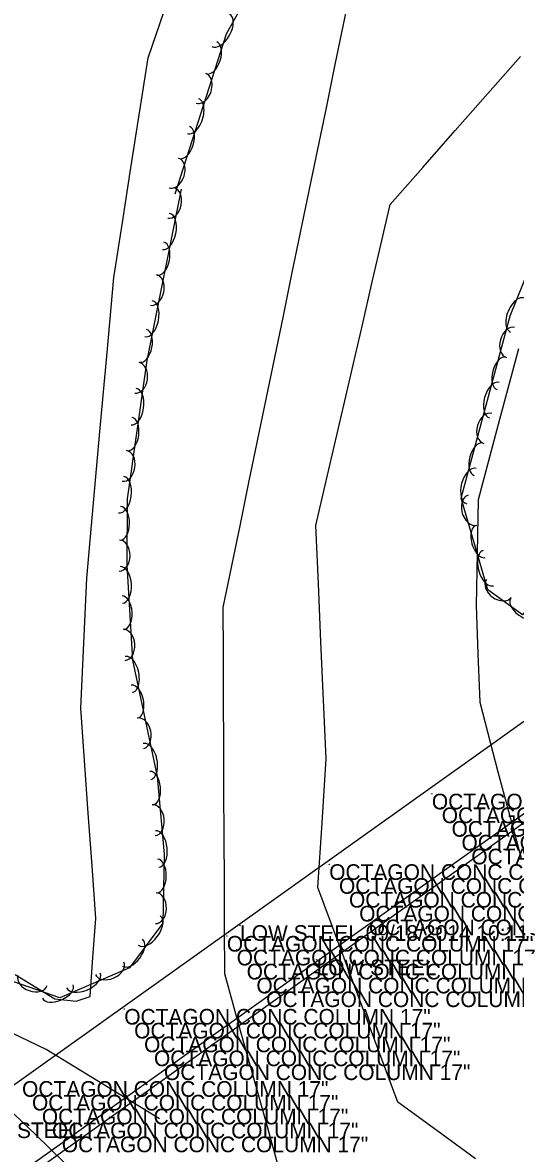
# Model space of a CAD drawing. Extents: x 1451369 to 1458940, y 1868647 to 1875095.
# Drawn here: x 1454280 to 1454437.4, y 1871458.6 to 1871820 of the extents above; entities that cross this region are included whole.
import ezdxf

# ---------------------------------------------------------------- set-up
doc = ezdxf.new("R2010")
doc.units = 0
for name, color, linetype in [('E_Existing_ROW', 7, 'Continuous'), ('E_Proposed ROW and Easements', 7, 'Continuous'), ('E_Quarter Section Line', 7, 'Continuous'), ('E_ROW Point Number', 7, 'Continuous'), ('E_Tract Residual', 7, 'Continuous'), ('S_EXIST_ROW', 7, 'Continuous'), ('S_MISC_STRUCTURES_ANNOT', 7, 'Continuous')]:
    doc.layers.add(name, color=color, linetype=linetype)

msp = doc.modelspace()

# ---------------------------------------------------------------- linework, layer by layer
at = {"layer": 'E_Existing_ROW'}
for p, q in [((1454539.16, 1871667.36), (1454213.66, 1871435.13)), ((1454227.64, 1871415.7), (1454553.13, 1871647.85))]:
    msp.add_line(p, q, dxfattribs=at)
at = {"layer": 'E_Proposed ROW and Easements'}
for points in [[(1454410.69, 1871573.56), (1454410.69, 1871573.61), (1454410.69, 1871573.56), (1454410.64, 1871573.56), (1454410.69, 1871573.56), (1454410.69, 1871573.51), (1454410.69, 1871573.56), (1454410.74, 1871573.56)], [(1454413.85, 1871569.17), (1454413.85, 1871569.22), (1454413.85, 1871569.17), (1454413.8, 1871569.17), (1454413.85, 1871569.17), (1454413.85, 1871569.12), (1454413.85, 1871569.17), (1454413.9, 1871569.17)], [(1454416.98, 1871564.83), (1454416.98, 1871564.88), (1454416.98, 1871564.83), (1454416.93, 1871564.83), (1454416.98, 1871564.83), (1454416.98, 1871564.78), (1454416.98, 1871564.83), (1454417.03, 1871564.83)], [(1454420.15, 1871560.41), (1454420.15, 1871560.46), (1454420.15, 1871560.41), (1454420.1, 1871560.41), (1454420.15, 1871560.41), (1454420.15, 1871560.36), (1454420.15, 1871560.41), (1454420.2, 1871560.41)], [(1454423.29, 1871555.99), (1454423.29, 1871556.04), (1454423.29, 1871555.99), (1454423.24, 1871555.99), (1454423.29, 1871555.99), (1454423.29, 1871555.94), (1454423.29, 1871555.99), (1454423.34, 1871555.99)], [(1454377.9, 1871551.02), (1454377.9, 1871551.07), (1454377.9, 1871551.02), (1454377.85, 1871551.02), (1454377.9, 1871551.02), (1454377.9, 1871550.97), (1454377.9, 1871551.02), (1454377.95, 1871551.02)], [(1454381.03, 1871546.59), (1454381.03, 1871546.64), (1454381.03, 1871546.59), (1454380.98, 1871546.59), (1454381.03, 1871546.59), (1454381.03, 1871546.54), (1454381.03, 1871546.59), (1454381.08, 1871546.59)], [(1454384.22, 1871542.16), (1454384.22, 1871542.21), (1454384.22, 1871542.16), (1454384.17, 1871542.16), (1454384.22, 1871542.16), (1454384.22, 1871542.11), (1454384.22, 1871542.16), (1454384.27, 1871542.16)], [(1454387.47, 1871537.73), (1454387.47, 1871537.78), (1454387.47, 1871537.73), (1454387.42, 1871537.73), (1454387.47, 1871537.73), (1454387.47, 1871537.68), (1454387.47, 1871537.73), (1454387.52, 1871537.73)], [(1454349.45, 1871531.54), (1454349.45, 1871531.59), (1454349.45, 1871531.54), (1454349.4, 1871531.54), (1454349.45, 1871531.54), (1454349.45, 1871531.49), (1454349.45, 1871531.54), (1454349.5, 1871531.54)], [(1454390.57, 1871533.33), (1454390.57, 1871533.38), (1454390.57, 1871533.33), (1454390.52, 1871533.33), (1454390.57, 1871533.33), (1454390.57, 1871533.28), (1454390.57, 1871533.33), (1454390.62, 1871533.33)], [(1454345.22, 1871528.1), (1454345.22, 1871528.15), (1454345.22, 1871528.1), (1454345.17, 1871528.1), (1454345.22, 1871528.1), (1454345.22, 1871528.05), (1454345.22, 1871528.1), (1454345.27, 1871528.1)], [(1454348.37, 1871523.69), (1454348.37, 1871523.74), (1454348.37, 1871523.69), (1454348.32, 1871523.69), (1454348.37, 1871523.69), (1454348.37, 1871523.64), (1454348.37, 1871523.69), (1454348.42, 1871523.69)], [(1454373.88, 1871520.55), (1454373.88, 1871520.6), (1454373.88, 1871520.55), (1454373.83, 1871520.55), (1454373.88, 1871520.55), (1454373.88, 1871520.5), (1454373.88, 1871520.55), (1454373.93, 1871520.55)], [(1454351.55, 1871519.2), (1454351.55, 1871519.25), (1454351.55, 1871519.2), (1454351.5, 1871519.2), (1454351.55, 1871519.2), (1454351.55, 1871519.15), (1454351.55, 1871519.2), (1454351.6, 1871519.2)], [(1454354.66, 1871514.74), (1454354.66, 1871514.79), (1454354.66, 1871514.74), (1454354.61, 1871514.74), (1454354.66, 1871514.74), (1454354.66, 1871514.69), (1454354.66, 1871514.74), (1454354.71, 1871514.74)], [(1454357.77, 1871510.37), (1454357.77, 1871510.42), (1454357.77, 1871510.37), (1454357.72, 1871510.37), (1454357.77, 1871510.37), (1454357.77, 1871510.32), (1454357.77, 1871510.37), (1454357.82, 1871510.37)], [(1454312.46, 1871504.77), (1454312.46, 1871504.82), (1454312.46, 1871504.77), (1454312.41, 1871504.77), (1454312.46, 1871504.77), (1454312.46, 1871504.72), (1454312.46, 1871504.77), (1454312.51, 1871504.77)], [(1454315.62, 1871500.34), (1454315.62, 1871500.39), (1454315.62, 1871500.34), (1454315.57, 1871500.34), (1454315.62, 1871500.34), (1454315.62, 1871500.29), (1454315.62, 1871500.34), (1454315.67, 1871500.34)], [(1454318.79, 1871495.92), (1454318.79, 1871495.97), (1454318.79, 1871495.92), (1454318.74, 1871495.92), (1454318.79, 1871495.92), (1454318.79, 1871495.87), (1454318.79, 1871495.92), (1454318.84, 1871495.92)], [(1454321.96, 1871491.48), (1454321.96, 1871491.53), (1454321.96, 1871491.48), (1454321.91, 1871491.48), (1454321.96, 1871491.48), (1454321.96, 1871491.43), (1454321.96, 1871491.48), (1454322.01, 1871491.48)], [(1454325.16, 1871487.04), (1454325.16, 1871487.09), (1454325.16, 1871487.04), (1454325.11, 1871487.04), (1454325.16, 1871487.04), (1454325.16, 1871486.99), (1454325.16, 1871487.04), (1454325.21, 1871487.04)], [(1454282.99, 1871477.31), (1454282.99, 1871477.36), (1454282.99, 1871477.31), (1454282.94, 1871477.31), (1454282.99, 1871477.31), (1454282.99, 1871477.26), (1454282.99, 1871477.31), (1454283.04, 1871477.31)], [(1454286.15, 1871472.87), (1454286.15, 1871472.92), (1454286.15, 1871472.87), (1454286.1, 1871472.87), (1454286.15, 1871472.87), (1454286.15, 1871472.82), (1454286.15, 1871472.87), (1454286.2, 1871472.87)], [(1454289.38, 1871468.41), (1454289.38, 1871468.46), (1454289.38, 1871468.41), (1454289.33, 1871468.41), (1454289.38, 1871468.41), (1454289.38, 1871468.36), (1454289.38, 1871468.41), (1454289.43, 1871468.41)], [(1454292.52, 1871463.97), (1454292.52, 1871464.02), (1454292.52, 1871463.97), (1454292.47, 1871463.97), (1454292.52, 1871463.97), (1454292.52, 1871463.92), (1454292.52, 1871463.97), (1454292.57, 1871463.97)]]:
    msp.add_lwpolyline(points, dxfattribs=at)
at = {"layer": 'E_Quarter Section Line'}
msp.add_line((1454551.64, 1871643.91), (1454234.22, 1871417.39), dxfattribs=at)
at = {"layer": 'E_ROW Point Number'}
for points in [[(1454474.53, 1872009.99), (1454468.45, 1871992.6), (1454458.03, 1871972.85), (1454441.05, 1871961.61), (1454416.35, 1871957.74), (1454397.06, 1871942.33), (1454383.25, 1871898.18), (1454368.69, 1871851.44), (1454357.73, 1871839.38), (1454344.98, 1871816.3), (1454328.66, 1871765.24)], [(1454738.31, 1871861.57), (1454708.8, 1871816.51), (1454693.32, 1871798.23), (1454669.26, 1871779.8), (1454629.46, 1871765.26), (1454608.9, 1871751.18), (1454586.75, 1871730.8), (1454560.06, 1871707.57), (1454538.95, 1871692.69), (1454521.86, 1871681.88), (1454502.43, 1871685.05), (1454482.33, 1871693.58), (1454468.83, 1871697.08), (1454462.33, 1871676.27), (1454453.21, 1871647.56), (1454439.65, 1871630.76), (1454428.53, 1871638.78), (1454420.08, 1871668), (1454435.67, 1871726.35), (1454455.54, 1871775.31), (1454484.24, 1871834.95)], [(1454330.64, 1871766.81), (1454319.69, 1871712.03), (1454313.42, 1871667.8), (1454313.27, 1871646.67), (1454315.11, 1871616.29), (1454322.93, 1871579.03), (1454325.24, 1871554.26), (1454324.81, 1871532.17), (1454314.16, 1871517.96), (1454291.89, 1871508.3), (1454234.83, 1871528.11)]]:
    msp.add_lwpolyline(points, dxfattribs=at)
for centre, major_axis, ratio, start_param, end_param in [((1454343.27, 1871817.57), (2.84, 5.14), 0.548521, 3.141593, 6.283185), ((1454340.35, 1871808.77), (1.62, 5.09), 0.539409, 3.140213, 6.281805), ((1454336.97, 1871799.04), (1.5, 4.72), 0.683674, 3.139264, 6.280857), ((1454334.4, 1871790.14), (1.78, 5.59), 0.548767, 3.140168, 6.281761), ((1454331.7, 1871781.7), (1.62, 5.09), 0.539409, 3.140213, 6.281805), ((1454328.32, 1871771.97), (1.5, 4.72), 0.683674, 3.139264, 6.280857), ((1454327.33, 1871762.42), (0.97, 4.86), 0.68531, 3.141593, 6.283185), ((1454325.77, 1871753.29), (1.15, 5.75), 0.550079, 3.141593, 6.283185), ((1454324.04, 1871744.59), (1.05, 5.24), 0.540699, 3.141593, 6.283185), ((1454321.76, 1871734.54), (0.97, 4.86), 0.68531, 3.141593, 6.283185), ((1454320.2, 1871725.41), (1.15, 5.75), 0.550079, 3.141593, 6.283185), ((1454438.03, 1871726.53), (-2.21, -5.44), 0.550022, 3.141578, 6.283171), ((1454435.85, 1871717.81), (-1.28, -4.79), 0.685234, 3.141593, 6.283185), ((1454318.46, 1871716.71), (1.05, 5.24), 0.540699, 3.141593, 6.283185), ((1454432.94, 1871707.92), (-1.38, -5.17), 0.540639, 3.141593, 6.283185), ((1454316.49, 1871706.47), (0.69, 4.91), 0.68531, 3.141593, 6.283185), ((1454430.65, 1871699.36), (-1.51, -5.67), 0.550018, 3.141593, 6.283185), ((1454315.45, 1871697.27), (0.82, 5.81), 0.550079, 3.141593, 6.283185), ((1454314.21, 1871688.49), (0.75, 5.29), 0.540699, 3.141593, 6.283185), ((1454428.52, 1871690.34), (-1.28, -4.79), 0.685234, 3.141593, 6.283185), ((1454312.51, 1871678.33), (0.69, 4.91), 0.68531, 3.141593, 6.283185), ((1454425.6, 1871680.46), (-1.38, -5.17), 0.540639, 3.141593, 6.283185), ((1454423.32, 1871671.89), (-1.51, -5.67), 0.550018, 3.141593, 6.283185), ((1454311.47, 1871669.12), (0.82, 5.81), 0.550079, 3.141593, 6.283185), ((1454423.66, 1871664.18), (1.38, -4.76), 0.685288, 3.141813, 6.283406), ((1454311.25, 1871659.98), (0.04, 5.35), 0.540698, 3.141593, 6.283185), ((1454426.27, 1871654.21), (1.48, -5.14), 0.540681, 3.141723, 6.283316), ((1454310.91, 1871649.68), (0.04, 4.96), 0.685308, 3.141593, 6.283185), ((1454428.74, 1871645.7), (1.63, -5.64), 0.550061, 3.141727, 6.28332), ((1454311.53, 1871640.29), (-0.35, 5.86), 0.550077, 3.141593, 6.283185), ((1454432.07, 1871639.17), (3.97, -2.87), 0.693211, 3.143251, 6.284843), ((1454312.07, 1871631.44), (-0.32, 5.34), 0.540697, 3.141593, 6.283185), ((1454440.17, 1871633), (4.29, -3.09), 0.546933, 3.142562, 6.284155), ((1454312.43, 1871621.14), (-0.3, 4.95), 0.685308, 3.141593, 6.283185), ((1454313.91, 1871611.69), (-1.2, 5.74), 0.55008, 3.141605, 6.283198), ((1454315.73, 1871603.01), (-1.1, 5.23), 0.5407, 3.141605, 6.283198), ((1454317.59, 1871592.88), (-1.02, 4.85), 0.685311, 3.141613, 6.283206), ((1454319.75, 1871583.87), (-1.2, 5.74), 0.55008, 3.141605, 6.283198), ((1454321.14, 1871575.37), (-0.5, 5.32), 0.540697, 3.141593, 6.283185), ((1454321.83, 1871565.09), (-0.46, 4.93), 0.685307, 3.141593, 6.283185), ((1454322.95, 1871555.89), (-0.54, 5.84), 0.550077, 3.141593, 6.283185), ((1454322.98, 1871547.27), (0.1, 5.35), 0.540698, 3.141593, 6.283185), ((1454322.52, 1871536.98), (0.1, 4.95), 0.685309, 3.141593, 6.283185), ((1454320.42, 1871529.84), (3.52, 4.7), 0.550079, 3.141593, 6.283185), ((1454315.1, 1871522.75), (3.21, 4.28), 0.540698, 3.141593, 6.283185), ((1454307.79, 1871517.79), (4.55, 1.97), 0.685302, 3.141593, 6.283185), ((1454283.17, 1871513.85), (4.68, -1.63), 0.685293, 3.141593, 6.283185), ((1454299.4, 1871513.87), (5.38, 2.34), 0.550073, 3.141593, 6.283185), ((1454291.27, 1871510.34), (4.9, 2.13), 0.540692, 3.141593, 6.283185)]:
    msp.add_ellipse(centre, major_axis=major_axis, ratio=ratio, start_param=start_param, end_param=end_param, dxfattribs=at)
at = {"layer": 'E_Tract Residual'}
for points in [[(1454277.67, 1871515.79), (1454290.34, 1871508.04), (1454297.14, 1871507.25), (1454301.52, 1871508.75), (1454302.43, 1871521.24), (1454303.34, 1871533.72), (1454302.16, 1871550.52), (1454300.98, 1871567.33), (1454299.8, 1871584.13), (1454298.62, 1871600.94), (1454299.54, 1871621.72), (1454300.47, 1871642.5), (1454302.63, 1871666.52), (1454304.8, 1871690.53), (1454306.96, 1871714.55), (1454309.13, 1871738.57), (1454311.86, 1871756.12), (1454314.59, 1871773.67), (1454317.32, 1871791.22), (1454320.05, 1871808.76), (1454325.15, 1871823.36), (1454330.24, 1871837.95), (1454335.34, 1871852.55), (1454340.44, 1871867.14)], [(1454438.33, 1871715.73), (1454431.88, 1871691.6), (1454425.43, 1871667.47), (1454425.12, 1871650.58), (1454424.82, 1871633.69), (1454425.42, 1871618.27), (1454426.03, 1871602.85), (1454431.74, 1871580.6), (1454435.49, 1871566.79), (1454439.25, 1871552.99)], [(1454028.63, 1871467.06), (1454040.93, 1871470.94), (1454053.22, 1871474.82), (1454065.52, 1871478.7), (1454085.99, 1871488.2), (1454106.46, 1871497.71), (1454123.82, 1871503.18), (1454141.18, 1871508.64), (1454158.54, 1871514.11), (1454175.9, 1871519.57), (1454197.42, 1871516.47), (1454210.05, 1871511.39), (1454222.68, 1871506.3), (1454236.48, 1871500.02), (1454251.25, 1871491.03), (1454266.03, 1871482.04), (1454275.12, 1871473.27), (1454284.21, 1871464.5), (1454293.3, 1871455.74)]]:
    msp.add_lwpolyline(points, dxfattribs=at)
at = {"layer": 'S_EXIST_ROW'}
for points in [[(1454362.7, 1871450.76), (1454358.17, 1871467.08), (1454353.63, 1871483.4), (1454349.09, 1871499.72), (1454344.55, 1871516.04), (1454344.49, 1871530.67), (1454344.42, 1871545.31), (1454344.36, 1871559.94), (1454344.3, 1871574.57), (1454344.23, 1871589.21), (1454344.17, 1871603.84), (1454344.1, 1871618.48), (1454344.04, 1871633.11), (1454346.79, 1871646.42), (1454349.53, 1871659.74), (1454352.28, 1871673.05), (1454355.03, 1871686.36), (1454357.77, 1871699.67), (1454360.52, 1871712.98), (1454363.27, 1871726.29), (1454366.02, 1871739.6), (1454368.76, 1871752.92), (1454371.51, 1871766.23), (1454374.26, 1871779.54), (1454377, 1871792.85), (1454379.75, 1871806.16), (1454382.5, 1871819.47), (1454385.24, 1871832.78)], [(1454424.6, 1871456.83), (1454412.24, 1871465.92), (1454399.87, 1871475.01), (1454393.48, 1871492.16), (1454387.09, 1871509.31), (1454380.7, 1871526.46), (1454374.31, 1871543.6), (1454375.61, 1871564.23), (1454376.91, 1871584.86), (1454376.09, 1871603.48), (1454375.28, 1871622.1), (1454374.46, 1871640.72), (1454373.65, 1871659.34), (1454376.62, 1871672.15), (1454379.59, 1871684.97), (1454382.56, 1871697.78), (1454385.53, 1871710.6), (1454388.49, 1871723.42), (1454391.46, 1871736.23), (1454394.43, 1871749.05), (1454397.4, 1871761.86), (1454407.79, 1871773.7), (1454418.18, 1871785.53), (1454428.57, 1871797.36), (1454438.96, 1871809.19)], [(1454323.73, 1871469.69), (1454305.65, 1871480.74), (1454287.57, 1871491.78), (1454270.84, 1871499.81), (1454254.11, 1871507.84)]]:
    msp.add_lwpolyline(points, dxfattribs=at)

# ---------------------------------------------------------------- texts
at = {"layer": 'S_MISC_STRUCTURES_ANNOT'}
for s, p in [('OCTAGON CONC COLUMN 17"', (1454410.69, 1871568.56)), ('OCTAGON CONC COLUMN 17"', (1454413.85, 1871564.17)), ('OCTAGON CONC COLUMN 17"', (1454416.98, 1871559.83)), ('OCTAGON CONC COLUMN 17"', (1454420.15, 1871555.41)), ('OCTAGON CONC COLUMN 17"', (1454423.29, 1871550.99)), ('OCTAGON CONC COLUMN 17"', (1454377.9, 1871546.02)), ('OCTAGON CONC COLUMN 17"', (1454381.03, 1871541.59)), ('OCTAGON CONC COLUMN 17"', (1454384.22, 1871537.16)), ('OCTAGON CONC COLUMN 17"', (1454387.47, 1871532.73)), ('LOW STEEL 09/18/2014 10:11:04', (1454349.45, 1871526.54)), ('OCTAGON CONC COLUMN 17"', (1454390.57, 1871528.33)), ('OCTAGON CONC COLUMN 17"', (1454345.22, 1871523.1)), ('OCTAGON CONC COLUMN 17"', (1454348.37, 1871518.69)), ('LOW STEEL', (1454373.88, 1871515.55)), ('OCTAGON CONC COLUMN 17"', (1454351.55, 1871514.2)), ('OCTAGON CONC COLUMN 17"', (1454354.66, 1871509.74)), ('OCTAGON CONC COLUMN 17"', (1454357.77, 1871505.37)), ('OCTAGON CONC COLUMN 17"', (1454312.46, 1871499.77)), ('OCTAGON CONC COLUMN 17"', (1454315.62, 1871495.34)), ('OCTAGON CONC COLUMN 17"', (1454318.79, 1871490.92)), ('OCTAGON CONC COLUMN 17"', (1454321.96, 1871486.48)), ('OCTAGON CONC COLUMN 17"', (1454325.16, 1871482.04)), ('OCTAGON CONC COLUMN 17"', (1454279.82, 1871476.69)), ('OCTAGON CONC COLUMN 17"', (1454282.99, 1871472.31)), ('OCTAGON CONC COLUMN 17"', (1454286.15, 1871467.87)), ('LOW STEEL', (1454261.12, 1871463.48)), ('OCTAGON CONC COLUMN 17"', (1454289.38, 1871463.41)), ('OCTAGON CONC COLUMN 17"', (1454292.52, 1871458.97))]:
    msp.add_text(s, height=5, dxfattribs=at).set_placement(p)

doc.saveas('drawing.dxf')
